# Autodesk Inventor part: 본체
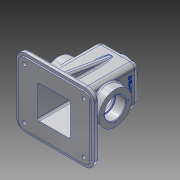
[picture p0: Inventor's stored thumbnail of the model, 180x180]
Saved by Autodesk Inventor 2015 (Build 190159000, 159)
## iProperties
Created: 2016-02
Part Number: 본체
Material: 알루미늄 6061
Document SubType Name: Modeling
Designer: Administrator
Density: 2.7 g/cm^3
Appearance: 알루미늄 - 평지
Mass: 855.968 g
Surface Area: 917.837 cm^2
Volume: 317.025 cm^3
Author: Administrator
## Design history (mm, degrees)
sketch "스케치1"
  geometry: L1 (-65, 57.5)-(65, 57.5); L2 (65, 57.5)-(65, -57.5); L3 (65, -57.5)-(-65, -57.5); L4 (-65, -57.5)-(-65, 57.5); L5 (-65, 57.5)-(65, -57.5); L6 (65, 57.5)-(-65, -57.5); 1 further point
  constraints: 12 end point, 2 midpoint, 2 parallel, 1 horizontal, 1 perpendicular
  dimensions: "d0" = 130 distance between parallel lines of L4 L2; "d1" = 115 distance between parallel lines of L1 L3
extrude "돌출1" new body sketch "스케치1" distance "d2" = 8; taper "d3" = 0 deg
sketch "스케치2"
  geometry: L1 (32.5, -32.5)-(-32.5, -32.5); L2 (-32.5, -32.5)-(-32.5, 32.5); L3 (-32.5, 32.5)-(32.5, 32.5); L4 (32.5, 32.5)-(32.5, -32.5); L5 (32.5, -32.5)-(-32.5, 32.5); L6 (-32.5, -32.5)-(32.5, 32.5); 1 further point
  constraints: 12 end point, 2 midpoint, 2 parallel, 1 horizontal, 1 perpendicular
  dimensions: "d4" = 65 distance between parallel lines of L4 L2; "d5" = 65 distance between parallel lines of L1 L3
extrude "돌출2" join sketch "스케치2" distance "d6" = 100; taper "d7" = 0 deg
sketch "스케치3"
  geometry: L1 (93.069, -32.5)-(8, -47.5); L2 (8, 57.5)-(8, -57.5) reference; L3 (8, -32.5)-(108, -32.5) reference; L4 (0, -57.5)-(8, -57.5) reference; L5 (41.261, 0)-(60.014, 0); L6 (93.069, 32.5)-(8, 47.5); L7 (93.069, -32.5)-(93.069, 32.5); L8 (8, 47.5)-(8, -47.5); 1 further point
  constraints: 10 end point, 2 point on line, 2 symmetric about line, 1 collinear, 1 horizontal, 1 vertical
  dimensions: "d8" = 80 deg angle of L2 L1; "d9" = 10 distance from line of L4 L1.end; "d10" = 0 distance from line of L5 point (0, 0)
extrude "돌출3" join sketch "스케치3" stored distance "d11" = 10; taper "d12" = 0 deg
sketch "스케치5"
  geometry: L1 (-42.5, 5.964)-(42.5, 5.964); L2 (42.5, 5.964)-(42.5, 55.964); L3 (42.5, 55.964)-(-42.5, 55.964); L4 (-42.5, 55.964)-(-42.5, 5.964); L5 (-42.5, 5.964)-(42.5, 55.964); L6 (42.5, 5.964)-(-42.5, 55.964); L7 (65, 0)-(65, 8) reference; L8 (32.5, 8)-(32.5, 108) reference; 2 further points
  constraints: 12 end point, 2 midpoint, 2 parallel, 1 horizontal, 1 perpendicular
  dimensions: "d13" = 0 horizontal distance of point (0, 0) point (0, 30.964); "d16" = 10 distance between parallel lines of L2 L8; "d17" = 50 distance of L1.end L2.end; "d18" = 5.96425 distance from line of L1 point (0, 0)
extrude "돌출4" join sketch "스케치5" stored distance "d19" = 6; taper "d20" = 0 deg
sketch "스케치6"
  geometry: L1 (0, -57.5)-(0, 57.5) reference; C1 r 27.5 at (53, 0); 1 further point
  constraints: 1 centre point
  dimensions: "d21" = 0 vertical distance of point (0, 0) C1.centre; "d22" = 55 diameter of C1; "d23" = 53 distance from line of L1 C1.centre
extrude "돌출5" join sketch "스케치6" stored distance "d24" = 95; taper "d25" = 0 deg
sketch "스케치7"
  geometry: L1 (47.5, 70.5)-(30.5, 70.5); L2 (30.5, 70.5)-(30.5, 68); L3 (30.5, 68)-(0, 68); L4 (-3.111, 53)-(47.5, 53); L5 (47.5, 53)-(47.5, 70.5); L6 (65, 0)-(-65, 0) reference; L7 (47.5, 25.5)-(47.5, 80.5) reference; L8 (-30.5, 68)-(0, 68); L9 (-30.5, 70.5)-(-30.5, 68); L10 (-47.5, 70.5)-(-30.5, 70.5); L11 (-47.5, 53)-(-47.5, 70.5); L12 (-3.111, 53)-(-47.5, 53); L13 (-47.5, 80.5)-(-47.5, 25.5) reference; 1 further point
  constraints: 20 end point, 4 horizontal, 3 perpendicular, 2 vertical
  dimensions: "d26" = 53 distance between parallel lines of L6 L4; "d27" = 15 distance between parallel lines of L4 L3; "d28" = 17.5 distance between parallel lines of L4 L1; "d29" = 17 distance from line of L5 L1.end; "d30" = 0 distance between parallel lines of L5 L7; "d34" = 17.5 distance of L11.start L10.start; "d35" = 17 distance of L10.start L9.start; "d36" = 0 distance between parallel lines of L13 L11
revolve "회전1" sketch "스케치7" stored, may be unused: angle "d37" = 90 deg
node "작업 평면1"
sketch "스케치8"
  geometry: L1 (-27.5, 27.5)-(27.5, 27.5); L2 (27.5, 27.5)-(27.5, -27.5); L3 (27.5, -27.5)-(-27.5, -27.5); L4 (-27.5, -27.5)-(-27.5, 27.5); L5 (-27.5, 27.5)-(27.5, -27.5); L6 (27.5, 27.5)-(-27.5, -27.5); L7 (32.5, -32.5)-(5, -32.5) reference; L8 (32.5, 27.5)-(32.5, -27.5) reference; 3 further points
  constraints: 12 end point, 2 midpoint, 2 parallel, 1 horizontal, 1 perpendicular
  dimensions: "d39" = 5 distance between parallel lines of L7 L3; "d40" = 5 distance between parallel lines of L8 L2
extrude "돌출6" cut sketch "스케치8" stored distance "d41" = 95; taper "d42" = 0 deg
node "작업 평면2"
sketch "스케치9"
  geometry: C1 r 20 at (0, 0); 1 further point
  constraints: 1 centre point, 1 coincident
  dimensions: "d44" = 40 diameter of C1
extrude "돌출7" join sketch "스케치9" stored distance "d45" = 95; taper "d46" = 0 deg
feature "면 기울기1" dims angle "d47" = 5 deg
sketch "스케치10" dims "d48" = 42
  geometry: A1 r 27.5 centre (0, 0) between (3, -27.336) and (-3, -27.336) reference; 6 further points
  constraints: 1 vertical alignment, 8 other
  dimensions: "d49" = 0 horizontal distance of point (0, 0) point (0, 21); "d52" = 360 deg dimension on point (0, 0) point (0, 21) (derived)
hole "구멍1" sketch "스케치10" at (0, 21), (-21, 0), (0, -21), (21, 0) diameter "d54" = 3.242; stored, may be unused: countersink angle "d58" = 90 deg, drill point angle "d60" = 118 deg; dims "d55" = 8, "d56" = 4, "d57" = 2, "d59" = 10
sketch "스케치11"
  geometry: C1 r 10.5 at (0, 0); C2 r 20.875 at (0, 0) reference; 1 further point
  constraints: 1 centre point, 1 concentric
  dimensions: "d61" = 21 diameter of C1
extrude "돌출8" cut sketch "스케치11" stored distance "d62" = 95; taper "d63" = 0 deg
sketch "스케치12" dims "d64" = 29
  geometry: C1 r 20 at (0, 0) reference; 9 further points
  constraints: 2 coincident, 2 horizontal alignment, 2 vertical alignment, 20 other
  dimensions: "d65" = 0 horizontal distance of point (0, 0) point (0, -14.5); "d68" = 360 deg dimension on point (0, 0) point (0, -14.5) (derived)
hole "구멍2" sketch "스케치12" at (0, -14.5), (14.5, 0), (0, 14.5), (-14.5, 0) diameter "d70" = 2.459; stored, may be unused: countersink angle "d74" = 90 deg, drill point angle "d76" = 118 deg; dims "d71" = 7, "d72" = 4, "d73" = 2, "d75" = 9
sketch "스케치13"
  geometry: L1 (-27.5, -15)-(-27.5, 15) reference; L2 (-65, -57.5)-(-65, 57.5) reference; L3 (-65, 57.5)-(65, 57.5) reference; C1 r 7.5 at (-50, 42.5); C2 r 7.5 at (50, 42.5); C3 r 7.5 at (-50, -42.5); C4 r 7.5 at (50, -42.5); 1 further point
  constraints: 4 centre point, 1 horizontal, 1 vertical, 6 other
  dimensions: "d77" = 15 diameter of C1; "d78" = 50 horizontal distance of C1.centre point (0, 0); "d79" = 42.5 vertical distance of point (0, 0) C1.centre; "d82" = 100 distance of C1.centre C2.centre; "d85" = 85 distance of C1.centre C3.centre
extrude "돌출9" join sketch "스케치13" distance "d88" = 11; taper "d89" = 0 deg
sketch "스케치14"
  geometry: L1 (27.5, -27.5)-(-27.5, -27.5) reference; L2 (27.5, 27.5)-(27.5, -27.5) reference; L3 (-27.5, -27.5)-(-27.5, 27.5) reference; L4 (-27.5, 27.5)-(27.5, 27.5) reference; L5 (-60, 52.5)-(60, 52.5); L6 (60, 52.5)-(60, -52.5); L7 (60, -52.5)-(-60, -52.5); L8 (-60, -52.5)-(-60, 52.5); L9 (-60, 52.5)-(60, -52.5); L10 (60, 52.5)-(-60, -52.5); 1 further point
  constraints: 12 end point, 2 midpoint, 2 parallel, 1 horizontal, 1 perpendicular
  dimensions: "d90" = 120 distance between parallel lines of L8 L6; "d91" = 105 distance between parallel lines of L7 L5
extrude "돌출10" join sketch "스케치14" distance "d92" = 2; taper "d93" = 0 deg
fillet "모깎기1" dims "d94" = 10
fillet "모깎기2" dims "d95" = 15
sketch "스케치15"
  geometry: L1 (-100, -15)-(0, -15) reference; L2 (15, 0)-(15, 85) reference; C1 r 3 at (0, 0); C2 r 7.5 at (0, 0) reference; C3 r 3 at (-100, 0); C4 r 3 at (0, 85); C5 r 3 at (-100, 85); 1 further point
  constraints: 4 centre point, 1 concentric, 1 horizontal, 1 vertical, 6 other
  dimensions: "d96" = 6 diameter of C1; "d99" = 100 distance of C1.centre C3.centre; "d102" = 85 distance of C1.centre C4.centre
extrude "돌출11" cut sketch "스케치15" stored distance "d105" = 2; taper "d106" = 0 deg
fillet "모깎기3" dims "d107" = 0.3
fillet "모깎기4" dims "d108" = 8
fillet "모깎기5" dims "d109" = 3
fillet "모깎기6" dims "d110" = 8
fillet "모깎기7" dims "d111" = 3
fillet "모깎기8" dims "d112" = 3
fillet "모깎기10" dims "d114" = 3
fillet "모깎기12" dims "d116" = 3
fillet "모깎기13" dims "d117" = 3
fillet "모깎기14" dims "d118" = 3
chamfer "모따기1" distance "d119" = 1; stored, may be unused: second distance "d120" = 2, angle "d121" = 45 deg
fillet "모깎기15" dims "d122" = 3
fillet "모깎기16" dims "d123" = 3
fillet "모깎기17" dims "d124" = 3
fillet "모깎기18" dims "d125" = 3
fillet "모깎기19" dims "d126" = 3
sketch "스케치16"
  geometry: L1 (-8, 0)-(-8, -92) reference; L2 (4.5, 18)-(44.5, 18) reference; 2 further points
  constraints: 1 other
  dimensions: "d127" = 32.5 distance from line of L1 point (24.5, -8); "d128" = 26 distance from line of L2 point (24.5, -8)
feature "엠보싱1" sketch "스케치16" dims "d129" = 0.5, "d130" = 0
fillet "모깎기20" dims "d131" = 1
node "솔리드1"
mirror "대칭1"
other parameters: "d38" = -5, "d43" = 118
